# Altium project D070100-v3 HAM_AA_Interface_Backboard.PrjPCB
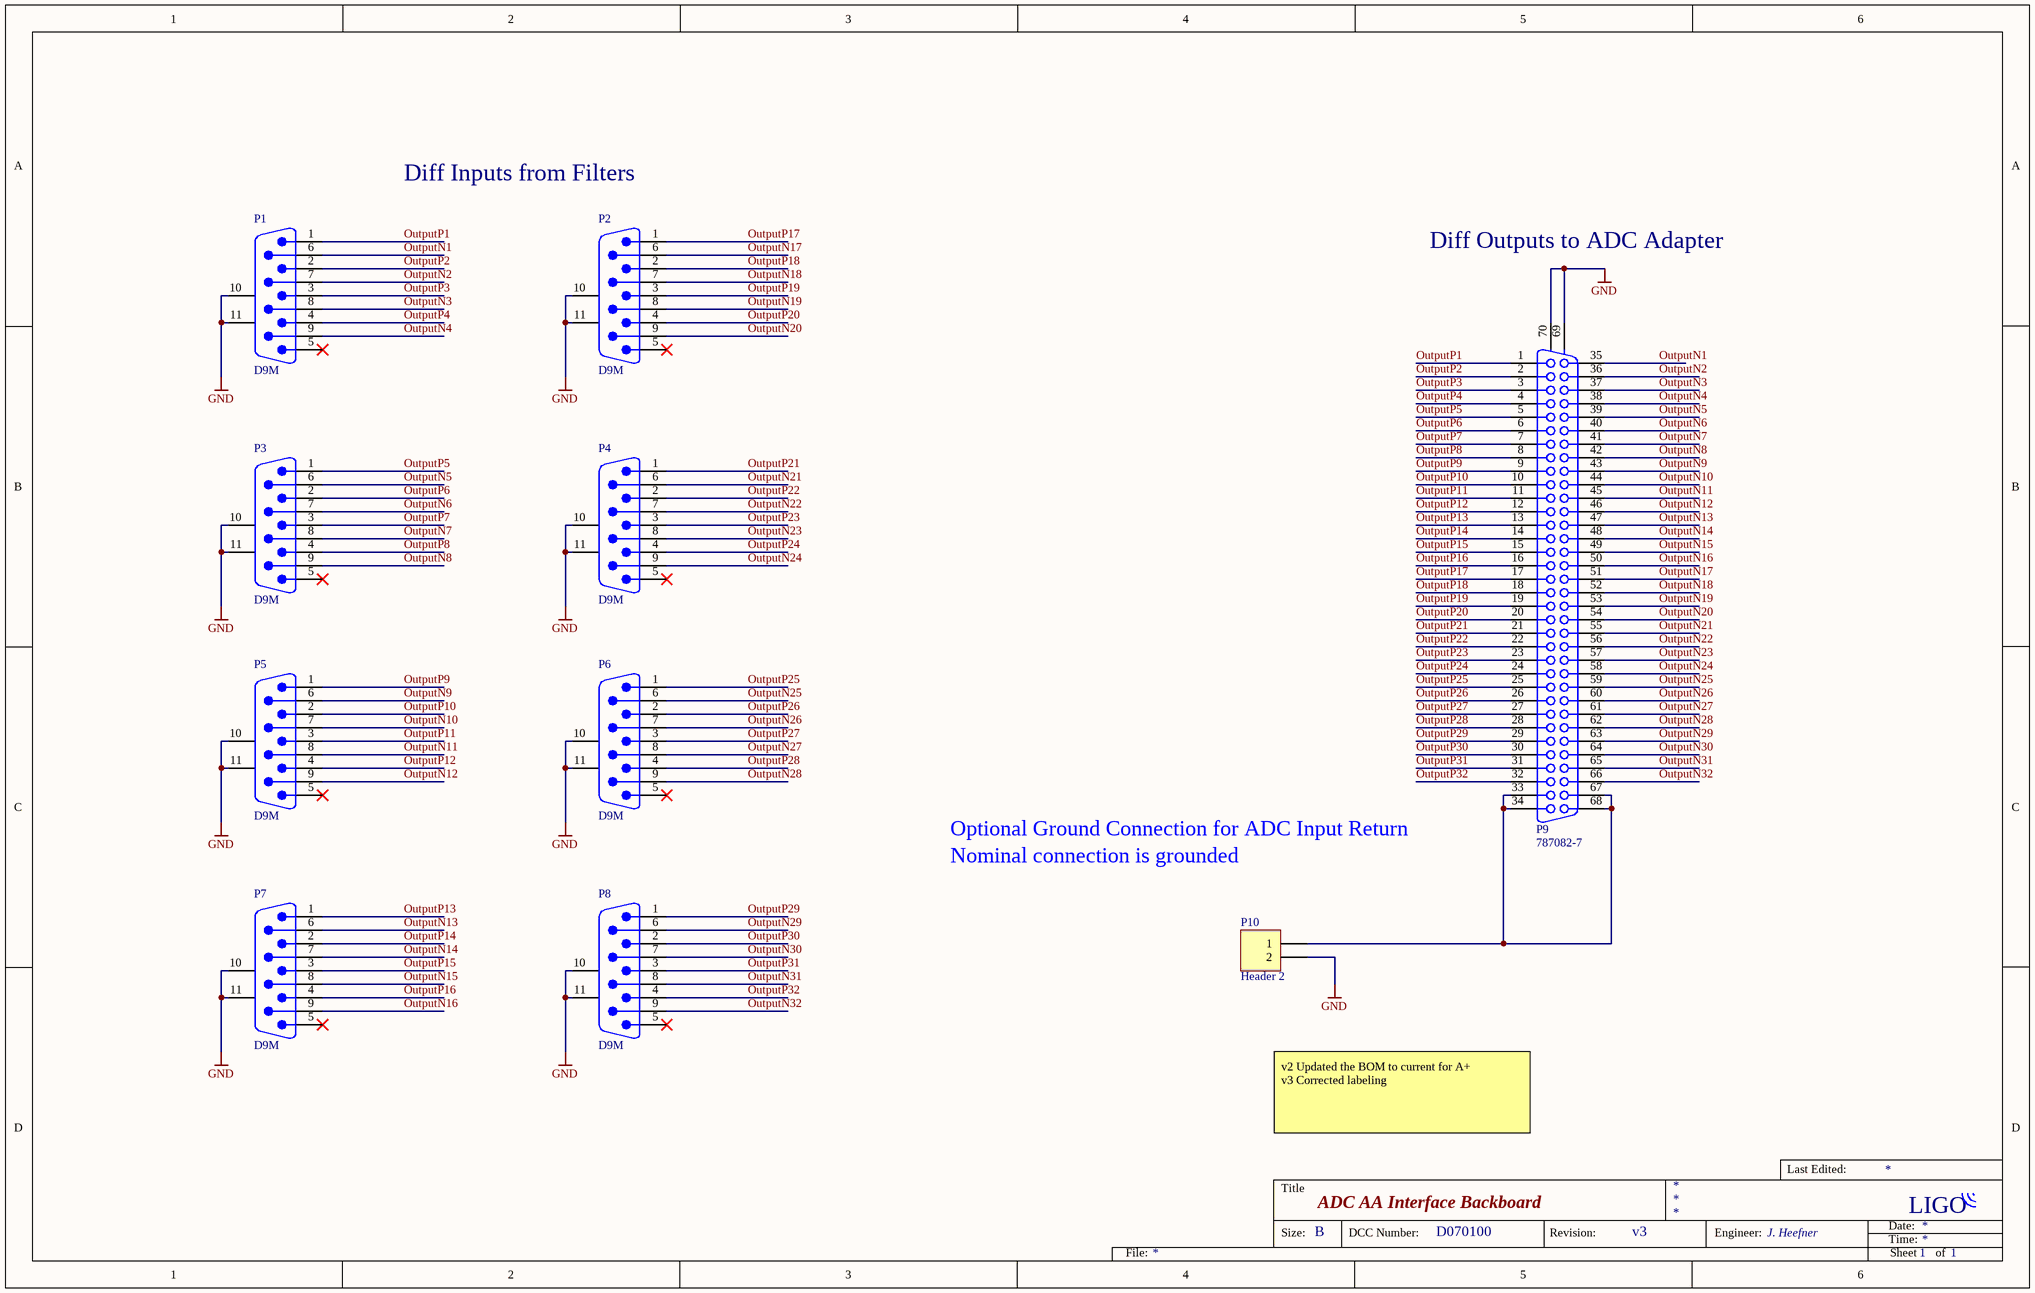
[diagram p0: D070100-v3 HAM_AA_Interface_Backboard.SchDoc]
1 sheet, 10 parts. Net scope: global (net labels, ports and power ports of the same name join across sheets).
Board file: D070100-v3 HAM_AA_Interface_Backboard.PcbDoc

## Sheet D070100-v3 HAM_AA_Interface_Backboard.SchDoc: ADC AA Interface Backboard
size B; DrawnBy: Dean Schaetzl; Engineer: J. Heefner; DocumentNumber: D070100; Revision: v3; SheetNumber: 1; SheetTotal: 1; PageSetup: Record=PageOptions¦CenterHorizontal=True¦CenterVertical=True¦PrintScale=0.52¦XCorrection=1.00¦YCorrection=1.00¦PrintKind=0¦BorderSize=5000000¦LeftOffset=0¦BottomOffset=0¦Orientation=2¦PaperLength=4318¦PaperWidth=2794¦Scale=100¦PaperSource=15¦PrintQuality=1200¦MediaType=1¦DitherType=10¦PaperKind=Tabloid¦PrintScaleMode=1

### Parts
P1  D9M  [DB9/M]
P2  D9M  [DB9/M]
P3  D9M  [DB9/M]
P4  D9M  [DB9/M]
P5  D9M  [DB9/M]
P6  D9M  [DB9/M]
P7  D9M  [DB9/M]
P8  D9M  [DB9/M]
P9  787082-7  [787082-7]
P10  Header 2  [HDR1X2]

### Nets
GND: P1.10(MH1) P1.11(MH2) P2.10(MH1) P2.11(MH2) P3.10(MH1) P3.11(MH2) P4.10(MH1) P4.11(MH2) P5.10(MH1) P5.11(MH2) P6.10(MH1) P6.11(MH2) P7.10(MH1) P7.11(MH2) P8.10(MH1) P8.11(MH2) P9.69(MH1) P9.70(MH2) P10.2
OutputN1: P1.6 P9.35
OutputN2: P1.7 P9.36
OutputN3: P1.8 P9.37
OutputN4: P1.9 P9.38
OutputN5: P3.6 P9.39
OutputN6: P3.7 P9.40
OutputN7: P3.8 P9.41
OutputN8: P3.9 P9.42
OutputN9: P5.6 P9.43
OutputN10: P5.7 P9.44
OutputN11: P5.8 P9.45
OutputN12: P5.9 P9.46
OutputN13: P7.6 P9.47
OutputN14: P7.7 P9.48
OutputN15: P7.8 P9.49
OutputN16: P7.9 P9.50
OutputN17: P2.6 P9.51
OutputN18: P2.7 P9.52
OutputN19: P2.8 P9.53
OutputN20: P2.9 P9.54
OutputN21: P4.6 P9.55
OutputN22: P4.7 P9.56
OutputN23: P4.8 P9.57
OutputN24: P4.9 P9.58
OutputN25: P6.6 P9.59
OutputN26: P6.7 P9.60
OutputN27: P6.8 P9.61
OutputN28: P6.9 P9.62
OutputN29: P8.6 P9.63
OutputN30: P8.7 P9.64
OutputN31: P8.8 P9.65
OutputN32: P8.9 P9.66
OutputP1: P1.1 P9.1
OutputP2: P1.2 P9.2
OutputP3: P1.3 P9.3
OutputP4: P1.4 P9.4
OutputP5: P3.1 P9.5
OutputP6: P3.2 P9.6
OutputP7: P3.3 P9.7
OutputP8: P3.4 P9.8
OutputP9: P5.1 P9.9
OutputP10: P5.2 P9.10
OutputP11: P5.3 P9.11
OutputP12: P5.4 P9.12
OutputP13: P7.1 P9.13
OutputP14: P7.2 P9.14
OutputP15: P7.3 P9.15
OutputP16: P7.4 P9.16
OutputP17: P2.1 P9.17
OutputP18: P2.2 P9.18
OutputP19: P2.3 P9.19
OutputP20: P2.4 P9.20
OutputP21: P4.1 P9.21
OutputP22: P4.2 P9.22
OutputP23: P4.3 P9.23
OutputP24: P4.4 P9.24
OutputP25: P6.1 P9.25
OutputP26: P6.2 P9.26
OutputP27: P6.3 P9.27
OutputP28: P6.4 P9.28
OutputP29: P8.1 P9.29
OutputP30: P8.2 P9.30
OutputP31: P8.3 P9.31
OutputP32: P8.4 P9.32
NetP9_33: P9.33 P9.34 P9.67 P9.68 P10.1

Not connected (* = marked no-connect by the designer): P1 5*; P2 5*; P3 5*; P4 5*; P5 5*; P6 5*; P7 5*; P8 5*

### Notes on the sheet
- Diff Inputs from Filters
- Diff Outputs to ADC Adapter
- Optional Ground Connection for ADC Input Return
- Nominal connection is grounded
- v2 Updated the BOM to current for A+
  v3 Corrected labeling

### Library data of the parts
P1-P8 = D9M: 9 Position D-Sub Plug, Male Pins Connector; Manufacturer: TE Connectivity; Manufacturer Part Number: 5747871-8; Plating: Tin; Body Material: Steel; Voltage Rating: 125V; Current Rating: 6A; Max Voltage Rating (DC): 250.25kV; Number of Positions: 9; Number of Ports: 1; Max Supply Voltage (AC): 250V; Mating Connector Lock: Yes (With); PCB Mount Retention: With; PCB Mounting Orientation: Vertical; Preloaded: Yes; Sealable: No (Without); Pitch: 0.108inch; PCB Thickness: 2.36mm; Contact Post Length: 0.125inch; Hole Diameter: 0.12inch; Approvals: UL
P9 = D68: 68 Position D-Type Receptacle, Female Sockets Connector; Manufacturer: TE Connectivity; Manufacturer Part Number: 7870827; Plating: Bright,Copper; Voltage Rating: 30V; Current Rating: 1A; Number of Positions: 68; Connector Type: Receptacle,Connector; Number of Ports: 1; Shielding: Shielded; Mating Alignment: No (Without); Mating Connector Lock: Yes (With); PCB Mount Retention: With; PCB Mounting Orientation: Right Angle; Pitch: 0.05inch; PCB Thickness: 1.57mm; Contact Post Length: 0.1inch; Hole Diameter: 0.109inch; Approvals: UL
P10 = Header 2: Connector Header Through Hole 2 position 0.100" (2.54mm); Manufacturer: Molex; Contact Resistance: 10mR; Max Current Rating: 4A; Voltage Rating: 250V; Number of Positions: 2; Gender: Male; Insulation Resistance: 500GR; Approvals: UL,CSA; Glow Wire Compliant: Non-compliant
